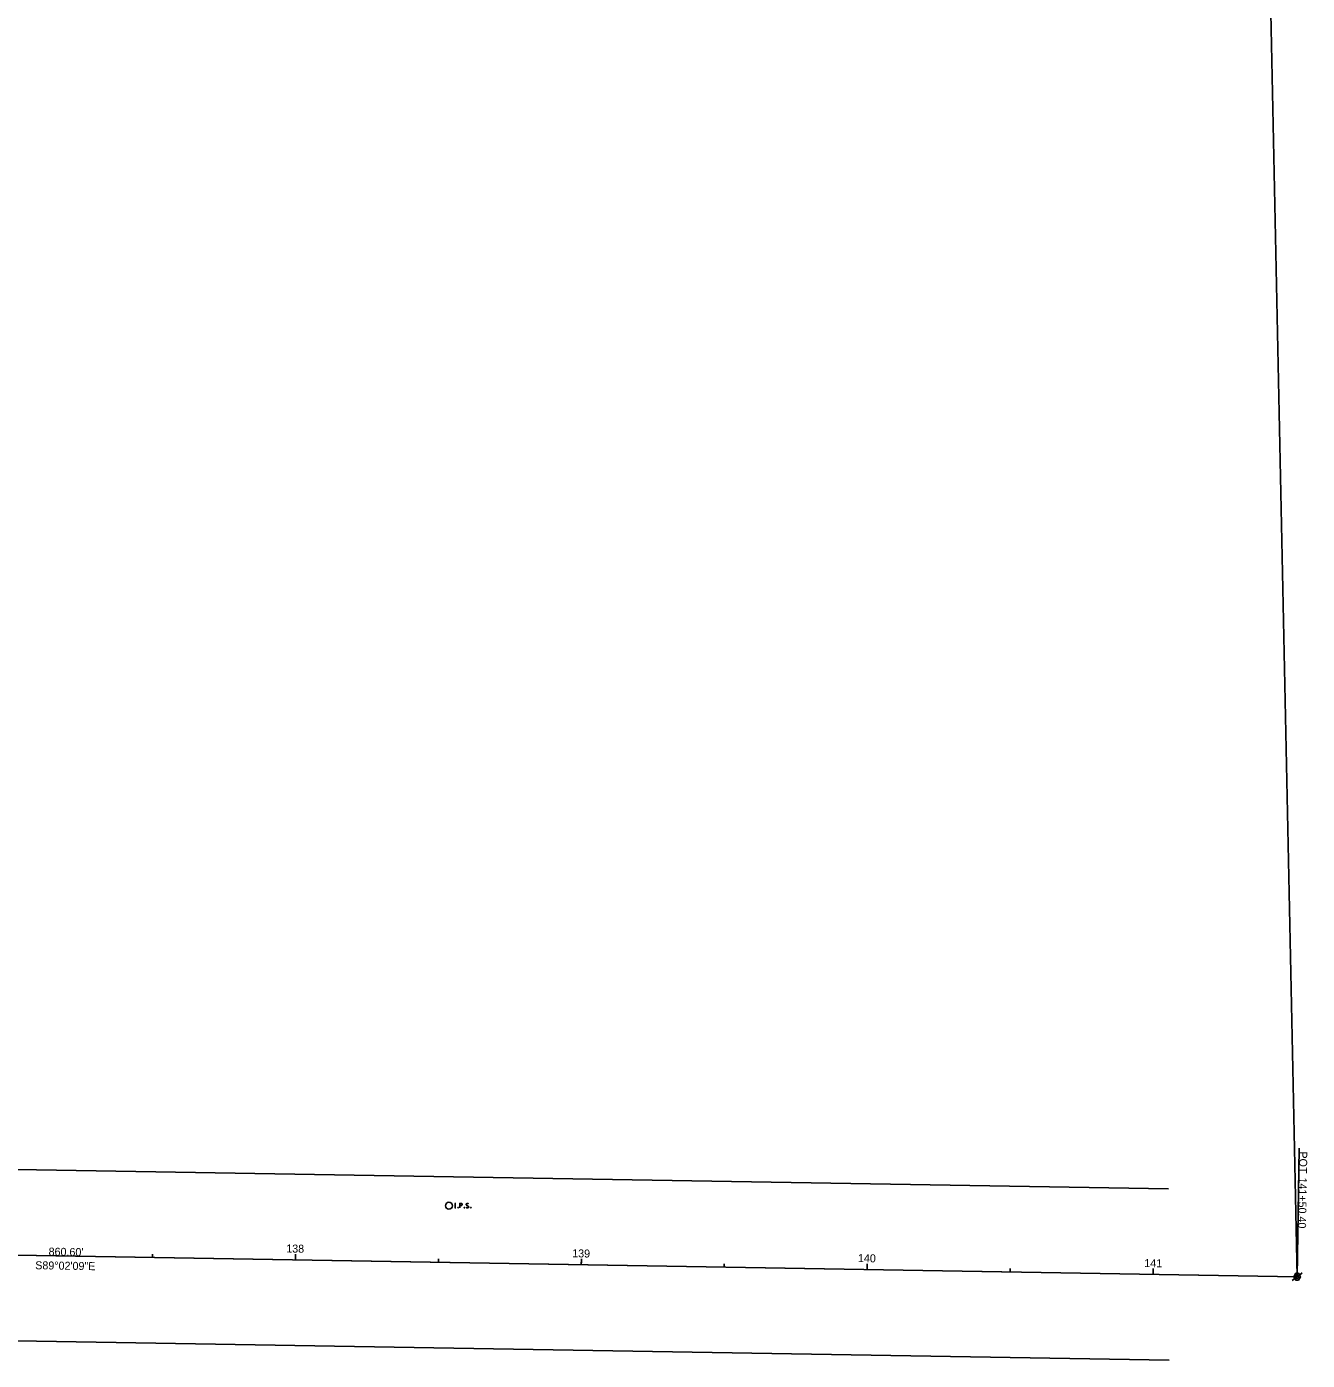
# Model space of a CAD drawing. Extents: x 2003596 to 2006888, y 571866 to 574416.
# Drawn here: x 2006439.7 to 2006887.7, y 572553.5 to 573020.2 of the extents above; entities that cross this region are included whole.
import ezdxf

# ---------------------------------------------------------------- set-up
doc = ezdxf.new("R2010")
doc.units = 0
for name, color, linetype in [('DV_X_Property_Line', 7, 'Continuous'), ('GE_X_Alignment', 7, 'Continuous'), ('GE_X_Alignment_1000_Bearings', 7, 'Continuous'), ('GE_X_Alignment_1000_Cardinal_Points', 7, 'Continuous'), ('GE_X_Alignment_1000_Distances', 7, 'Continuous'), ('GE_X_Alignment_1000_Stations', 7, 'Continuous'), ('GE_X_Alignment_100_Bearings', 7, 'Continuous'), ('GE_X_Alignment_100_Cardinal_Points', 7, 'Continuous'), ('GE_X_Alignment_100_Distances', 7, 'Continuous'), ('GE_X_Alignment_100_Stations', 7, 'Continuous'), ('GE_X_Alignment_500_Bearings', 7, 'Continuous'), ('GE_X_Alignment_500_Cardinal_Points', 7, 'Continuous'), ('GE_X_Alignment_500_Distances', 7, 'Continuous'), ('GE_X_Alignment_500_Stations', 7, 'Continuous'), ('RW_X_CL', 7, 'Continuous'), ('RW_X_Esmt_SH', 7, 'Continuous'), ('SC_Scratch9', 7, 'Continuous'), ('SV_P_Mon_Cells_Set', 7, 'Continuous'), ('SV_X_Control_Cells_Found', 7, 'Continuous')]:
    doc.layers.add(name, color=color, linetype=linetype)

msp = doc.modelspace()

# ---------------------------------------------------------------- linework, layer by layer
at = {"layer": 'DV_X_Property_Line'}
msp.add_line((2006865.66, 573476.51), (2006884.1, 572582.77), dxfattribs=at)
at = {"layer": 'GE_X_Alignment'}
msp.add_line((2006023.62, 572597.25), (2006884.1, 572582.77), dxfattribs=at)
at = {"layer": 'GE_X_Alignment_1000_Cardinal_Points'}
msp.add_line((2006884.1, 572582.77), (2006884.86, 572627.76), dxfattribs=at)
msp.add_circle((2006884.1, 572582.77), 0.6, dxfattribs=at)
at = {"layer": 'GE_X_Alignment_1000_Stations'}
msp.add_line((2006733.72, 572585.3), (2006733.75, 572587.3), dxfattribs=at)
at = {"layer": 'GE_X_Alignment_100_Cardinal_Points'}
msp.add_line((2006884.1, 572582.77), (2006884.86, 572627.76), dxfattribs=at)
msp.add_circle((2006884.1, 572582.77), 0.6, dxfattribs=at)
at = {"layer": 'GE_X_Alignment_100_Stations'}
for p, q in [((2006483.76, 572589.51), (2006483.78, 572590.71)), ((2006533.75, 572588.67), (2006533.78, 572590.67)), ((2006583.74, 572587.82), (2006583.76, 572589.02)), ((2006633.73, 572586.98), (2006633.77, 572588.98)), ((2006683.73, 572586.14), (2006683.75, 572587.34)), ((2006733.72, 572585.3), (2006733.75, 572587.3)), ((2006783.71, 572584.46), (2006783.73, 572585.66)), ((2006833.71, 572583.62), (2006833.74, 572585.62)), ((2006883.7, 572582.78), (2006883.72, 572583.98))]:
    msp.add_line(p, q, dxfattribs=at)
at = {"layer": 'GE_X_Alignment_500_Cardinal_Points'}
msp.add_line((2006884.1, 572582.77), (2006884.86, 572627.76), dxfattribs=at)
msp.add_circle((2006884.1, 572582.77), 0.6, dxfattribs=at)
at = {"layer": 'GE_X_Alignment_500_Stations'}
for p, q in [((2006533.75, 572588.67), (2006533.77, 572589.87)), ((2006633.73, 572586.98), (2006633.75, 572588.18)), ((2006733.72, 572585.3), (2006733.75, 572587.3)), ((2006833.71, 572583.62), (2006833.73, 572584.82))]:
    msp.add_line(p, q, dxfattribs=at)
at = {"layer": 'RW_X_CL'}
msp.add_line((2006884.1, 572582.77), (2006023.62, 572597.25), dxfattribs=at)
at = {"layer": 'RW_X_Esmt_SH'}
for p, q in [((2006024.45, 572627.24), (2006839.11, 572613.53)), ((2006022.8, 572567.26), (2006839.37, 572553.52))]:
    msp.add_line(p, q, dxfattribs=at)
at = {"layer": 'SC_Scratch9'}
msp.add_line((2006884.1, 572582.77), (2006371.52, 572591.34), dxfattribs=at)
at = {"layer": 'SV_P_Mon_Cells_Set'}
for points in [[(2006589.46, 572608.43), (2006589.82, 572608.43)], [(2006589.46, 572606.83), (2006589.82, 572606.83)], [(2006589.64, 572606.83), (2006589.64, 572608.43)], [(2006590.6, 572607.05), (2006590.65, 572607.05), (2006590.69, 572607.02), (2006590.72, 572606.97), (2006590.72, 572606.91), (2006590.69, 572606.86), (2006590.65, 572606.83), (2006590.6, 572606.83), (2006590.57, 572606.86), (2006590.53, 572606.91), (2006590.53, 572606.97), (2006590.57, 572607.02), (2006590.6, 572607.05)], [(2006591.2, 572606.83), (2006591.2, 572608.43), (2006591.73, 572608.43), (2006591.79, 572608.42), (2006591.87, 572608.39), (2006591.9, 572608.37), (2006591.93, 572608.34), (2006591.98, 572608.28), (2006592.01, 572608.22), (2006592.03, 572608.12), (2006592.03, 572607.97), (2006592.02, 572607.92), (2006592, 572607.84), (2006591.95, 572607.75), (2006591.91, 572607.71), (2006591.88, 572607.69), (2006591.82, 572607.66), (2006591.73, 572607.65), (2006591.2, 572607.65)], [(2006592.85, 572607.05), (2006592.9, 572607.05), (2006592.94, 572607.02), (2006592.97, 572606.97), (2006592.97, 572606.91), (2006592.94, 572606.86), (2006592.9, 572606.83), (2006592.85, 572606.83), (2006592.81, 572606.86), (2006592.78, 572606.91), (2006592.78, 572606.97), (2006592.81, 572607.02), (2006592.85, 572607.05)], [(2006594.21, 572608.32), (2006594.19, 572608.34), (2006594.16, 572608.37), (2006594.06, 572608.41), (2006593.94, 572608.43), (2006593.85, 572608.43), (2006593.82, 572608.43), (2006593.67, 572608.39), (2006593.55, 572608.32), (2006593.48, 572608.22), (2006593.45, 572608.12), (2006593.45, 572608.04), (2006593.48, 572607.94), (2006593.56, 572607.85), (2006594.17, 572607.47), (2006594.22, 572607.42), (2006594.25, 572607.37), (2006594.27, 572607.3), (2006594.27, 572607.22), (2006594.26, 572607.15), (2006594.25, 572607.1), (2006594.22, 572607.03), (2006594.2, 572606.98), (2006594.18, 572606.95), (2006594.15, 572606.91), (2006594.11, 572606.88), (2006594.07, 572606.86), (2006594.04, 572606.84), (2006593.94, 572606.83), (2006593.78, 572606.83), (2006593.68, 572606.86), (2006593.54, 572606.95), (2006593.45, 572607.02)], [(2006595.03, 572607.05), (2006595.08, 572607.05), (2006595.12, 572607.02), (2006595.15, 572606.97), (2006595.15, 572606.91), (2006595.12, 572606.86), (2006595.08, 572606.83), (2006595.03, 572606.83), (2006595, 572606.86), (2006594.96, 572606.91), (2006594.96, 572606.97), (2006595, 572607.02), (2006595.03, 572607.05)]]:
    msp.add_lwpolyline(points, dxfattribs=at)
msp.add_circle((2006587.44, 572607.63), 1.2, dxfattribs=at)
at = {"layer": 'SV_X_Control_Cells_Found'}
for p, q in [((2006883.3, 572582.17), (2006882.33, 572581.45)), ((2006885.87, 572584.09), (2006884.91, 572583.37))]:
    msp.add_line(p, q, dxfattribs=at)
msp.add_lwpolyline([(2006883.65, 572583.97), (2006884.55, 572583.97), (2006885.26, 572582.77), (2006884.55, 572581.57), (2006883.65, 572581.57), (2006882.94, 572582.77)], close=True, dxfattribs=at)

# ---------------------------------------------------------------- texts
at = {"layer": 'GE_X_Alignment_1000_Bearings'}
msp.add_text('S89°02\'09"E', height=2.8, rotation=359.0359, dxfattribs=at).set_placement((2006442.71, 572585.4))
at = {"layer": 'GE_X_Alignment_1000_Cardinal_Points'}
for s, p in [('POT', (2006884.89, 572626.64)), ('141+50.40', (2006884.73, 572617.51))]:
    msp.add_text(s, height=2.8, rotation=269.0359, dxfattribs=at).set_placement(p)
at = {"layer": 'GE_X_Alignment_1000_Distances'}
msp.add_text("860.60'", height=2.8, rotation=359.0359, dxfattribs=at).set_placement((2006447.38, 572590.17))
at = {"layer": 'GE_X_Alignment_1000_Stations'}
msp.add_text('140', height=2.8, rotation=359.0359, dxfattribs=at).set_placement((2006730.48, 572587.9))
at = {"layer": 'GE_X_Alignment_100_Bearings'}
msp.add_text('S89°02\'09"E', height=2.8, rotation=359.0359, dxfattribs=at).set_placement((2006442.71, 572585.4))
at = {"layer": 'GE_X_Alignment_100_Cardinal_Points'}
for s, p in [('POT', (2006884.89, 572626.64)), ('141+50.40', (2006884.73, 572617.51))]:
    msp.add_text(s, height=2.8, rotation=269.0359, dxfattribs=at).set_placement(p)
at = {"layer": 'GE_X_Alignment_100_Distances'}
msp.add_text("860.60'", height=2.8, rotation=359.0359, dxfattribs=at).set_placement((2006447.38, 572590.17))
at = {"layer": 'GE_X_Alignment_100_Stations'}
for s, p in [('138', (2006530.51, 572591.27)), ('139', (2006630.53, 572589.58)), ('140', (2006730.48, 572587.9)), ('141', (2006830.64, 572586.17))]:
    msp.add_text(s, height=2.8, rotation=359.0359, dxfattribs=at).set_placement(p)
at = {"layer": 'GE_X_Alignment_500_Bearings'}
msp.add_text('S89°02\'09"E', height=2.8, rotation=359.0359, dxfattribs=at).set_placement((2006442.71, 572585.4))
at = {"layer": 'GE_X_Alignment_500_Cardinal_Points'}
for s, p in [('POT', (2006884.89, 572626.64)), ('141+50.40', (2006884.73, 572617.51))]:
    msp.add_text(s, height=2.8, rotation=269.0359, dxfattribs=at).set_placement(p)
at = {"layer": 'GE_X_Alignment_500_Distances'}
msp.add_text("860.60'", height=2.8, rotation=359.0359, dxfattribs=at).set_placement((2006447.38, 572590.17))
at = {"layer": 'GE_X_Alignment_500_Stations'}
msp.add_text('140', height=2.8, rotation=359.0359, dxfattribs=at).set_placement((2006730.48, 572587.9))

doc.saveas('drawing.dxf')
